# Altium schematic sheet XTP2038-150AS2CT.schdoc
size 127 x 101 mm
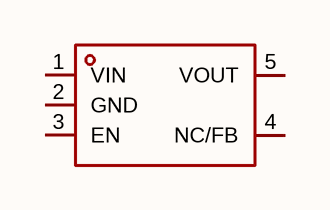
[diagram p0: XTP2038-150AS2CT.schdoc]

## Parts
U?  xtp2038-150as2ct  [SOT-23-5_L2.9-W1.6-P0.95-LS2.8-BR]  (value not drawn)

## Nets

Not connected (* = marked no-connect by the designer): U? 1(VIN) 2(GND) 3(EN) 4(NC/FB) 5(VOUT)

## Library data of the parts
U? = xtp2038-150as2ct: 输出极性:正极;工作电压:5.5V;输出电压:1.5V;输出电流:500mA;电源纹波抑制比(PSRR):-;输出类型:固定;; Manufacturer: XTX(芯天下); AddInBom: yes; ModelId: 7ba65df16e7b4570af156e925f9c37fe; ModelTransform: 114.173,114.173,0,90,0,0,0,0,0; Output Configuration: 正极; Voltage - Supply: 5.5V; Output Voltage: 1.5V; Output Current: 500mA; Voltage Dropout: 180mV@(300mA); standby current: 15uA; Output Type: 固定; Number of Outputs: 1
